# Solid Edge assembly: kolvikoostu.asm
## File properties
Author: Türk
Template: Iso Assembly.asm
Last saved by: Türk
Revision: 5
Application: Solid Edge
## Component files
Kolv 2.par
ngas1.par
ngas2.par
kepsu pulk.par
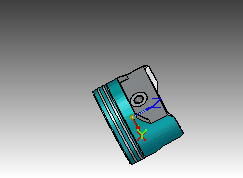
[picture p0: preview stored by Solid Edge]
